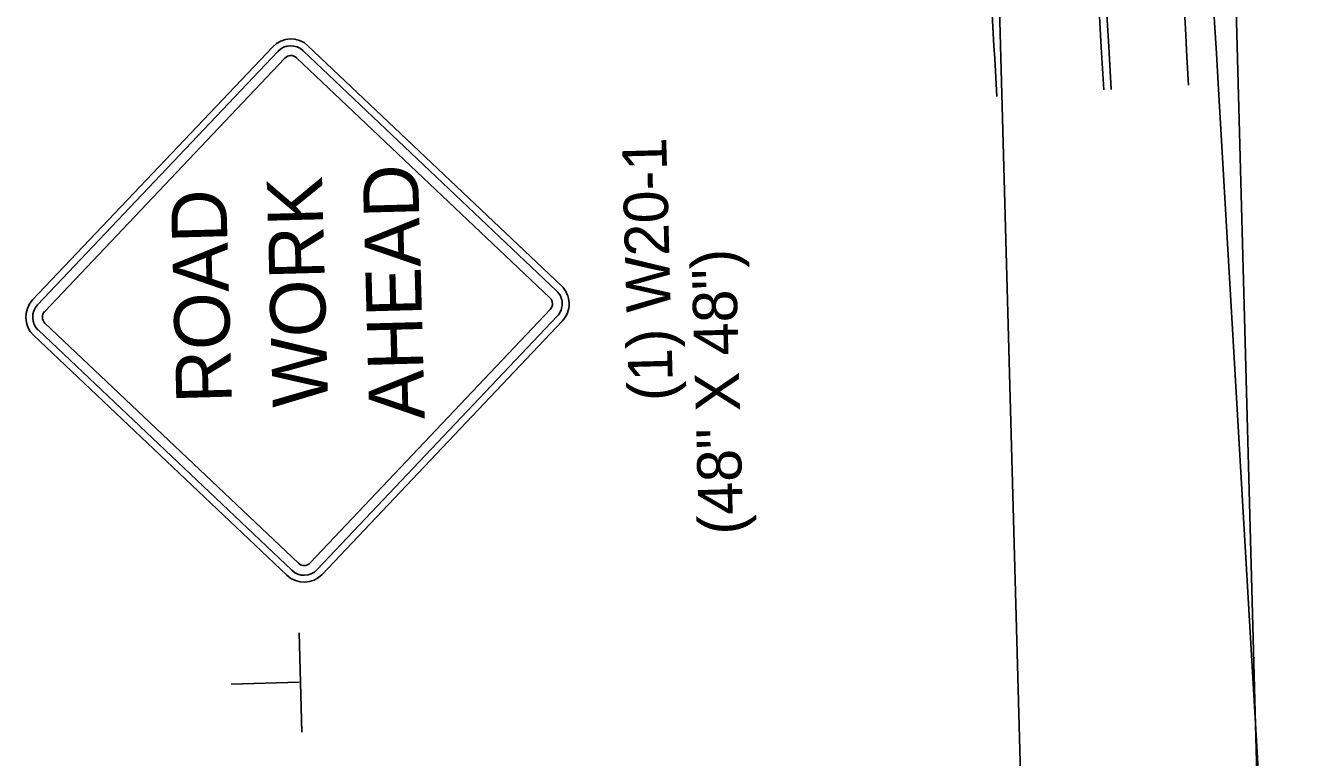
# Model space of a CAD drawing. Extents: x 1929653 to 1931621, y 596452 to 600944.
# Drawn here: x 1929652.7 to 1929914.5, y 598058.5 to 598207.1 of the extents above; entities that cross this region are included whole.
import ezdxf

# ---------------------------------------------------------------- set-up
doc = ezdxf.new("R2010")
doc.units = 0
for name, color, linetype in [('G-ANNO-NPLT', 7, 'Continuous'), ('P_TC_Signs_Temporary', 7, 'Continuous'), ('R_Border', 7, 'Continuous'), ('R_Draft', 7, 'Continuous')]:
    doc.layers.add(name, color=color, linetype=linetype)

msp = doc.modelspace()

# ---------------------------------------------------------------- linework, layer by layer
at = {"layer": 'G-ANNO-NPLT'}
msp.add_arc((1935592.2, 598528.17), 5752.08, 182.523795, 183.343096, dxfattribs=at)
at = {"layer": 'P_TC_Signs_Temporary'}
for p, q in [((1929702.88, 598202.82), (1929654.13, 598151.38)), ((1929703.9, 598201.86), (1929655.15, 598150.41)), ((1929760.52, 598153.24), (1929709.07, 598201.99)), ((1929761.48, 598154.26), (1929710.04, 598203.01)), ((1929705.33, 598200.5), (1929656.58, 598149.06)), ((1929759.16, 598151.81), (1929707.72, 598200.56)), ((1929710.47, 598097.98), (1929759.23, 598149.43)), ((1929656.64, 598146.67), (1929708.09, 598097.92)), ((1929711.9, 598096.63), (1929760.65, 598148.07)), ((1929712.92, 598095.66), (1929761.67, 598147.1)), ((1929654.32, 598144.22), (1929705.76, 598095.47)), ((1929655.29, 598145.24), (1929706.73, 598096.49))]:
    msp.add_line(p, q, dxfattribs=at)
for centre, radius, start, end in [((1929706.56, 598199.34), 5.06, 46.5377, 136.5377), ((1929706.56, 598199.34), 3.66, 46.5377, 136.5377), ((1929706.56, 598199.34), 1.69, 46.5377, 136.5377), ((1929758, 598150.59), 3.66, 316.5377, 46.5377), ((1929758, 598150.59), 5.06, 316.5377, 46.5377), ((1929657.8, 598147.9), 5.06, 136.5377, 226.5377), ((1929657.8, 598147.9), 3.66, 136.5377, 226.5377), ((1929758, 598150.59), 1.69, 316.5377, 46.5377), ((1929657.8, 598147.9), 1.69, 136.5377, 226.5377), ((1929709.25, 598099.14), 1.69, 226.5377, 316.5377), ((1929709.25, 598099.14), 5.06, 226.5377, 316.5377), ((1929709.25, 598099.14), 3.66, 226.5377, 316.5377)]:
    msp.add_arc(centre, radius, start, end, dxfattribs=at)
at = {"layer": 'R_Draft'}
for p, q in [((1929860.13, 597856.47), (1929835.62, 598755.2)), ((1929907.99, 597857.75), (1929883.87, 598756.49)), ((1929914.54, 597857.93), (1929894.83, 598195.36)), ((1929708.24, 598083.8), (1929708.79, 598063.61)), ((1929708.22, 598073.74), (1929694.44, 598073.37))]:
    msp.add_line(p, q, dxfattribs=at)
for centre, radius, start, end in [((1935591.45, 598528.15), 5729.58, 177.7558, 183.343096), ((1935591.45, 598528.15), 5728.08, 177.76852, 183.3431), ((1935592.2, 598528.17), 5707.08, 179.37471, 183.3431), ((1935592.2, 598528.17), 5713.08, 179.63853, 183.3431)]:
    msp.add_arc(centre, radius, start, end, dxfattribs=at)

# ---------------------------------------------------------------- texts
at = {"layer": 'P_TC_Signs_Temporary'}
for s, p in [(' AHEAD ', (1929733.86, 598123.06)), ('WORK', (1929714.14, 598129.79)), (' ROAD ', (1929694.69, 598126.35))]:
    msp.add_text(s, height=11.25, rotation=91.5377, dxfattribs=at).set_placement(p)
at = {"layer": 'R_Border'}
for s, p in [('(1) W20-1', (1929784.2, 598130.96)), ('(48" X 48")', (1929798.43, 598103.83))]:
    msp.add_text(s, height=9, rotation=91.5377, dxfattribs=at).set_placement(p)

doc.saveas('drawing.dxf')
